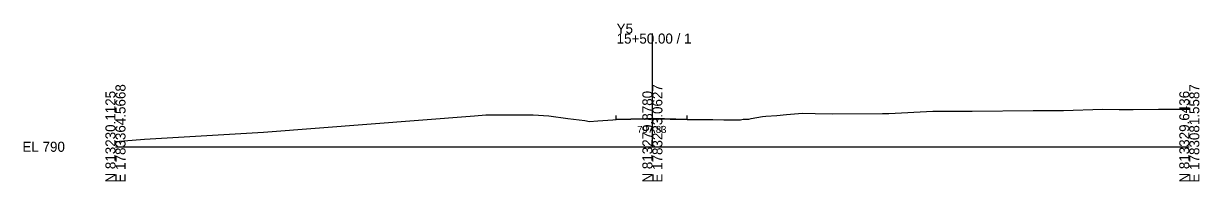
# Model space of a CAD drawing. Extents: x -26 to 1603, y -10 to 6526.
# Drawn here: x 1274.3 to 1602.8, y 2490.3 to 2534.4 of the extents above; entities that cross this region are included whole.
import ezdxf

# ---------------------------------------------------------------- set-up
doc = ezdxf.new("R2010")
doc.units = 0
for name, color, linetype in [('Exist Cross Section Cell', 7, 'Continuous'), ('Exist XS Center Line Elevation Label', 7, 'Continuous'), ('Exist XS Ground Line', 7, 'Continuous'), ('Prop XS EOT Tick Mark', 7, 'Continuous'), ('Prop XS Finish Grade Pavement', 7, 'Continuous')]:
    doc.layers.add(name, color=color, linetype=linetype)

msp = doc.modelspace()

# ---------------------------------------------------------------- linework, layer by layer
at = {"layer": 'Exist Cross Section Cell'}
for p, q in [((1450, 2500), (1450, 2531.62)), ((1300, 2500), (1450, 2500)), ((1450, 2500), (1600, 2500))]:
    msp.add_line(p, q, dxfattribs=at)
at = {"layer": 'Exist XS Ground Line'}
for p, q in [((1528.38, 2509.91), (1535.36, 2509.99)), ((1535.36, 2509.99), (1539.38, 2509.98)), ((1539.38, 2509.98), (1556.34, 2510.1)), ((1556.34, 2510.1), (1561.19, 2510.12)), ((1561.19, 2510.12), (1564.88, 2510.16)), ((1564.88, 2510.16), (1575.76, 2510.48)), ((1575.76, 2510.48), (1580.4, 2510.38)), ((1580.4, 2510.38), (1584.29, 2510.42)), ((1584.29, 2510.42), (1591.41, 2510.54)), ((1591.41, 2510.54), (1600, 2510.51)), ((1341.36, 2504.09), (1400.33, 2508.66)), ((1400.33, 2508.66), (1403.42, 2508.88)), ((1403.42, 2508.88), (1403.84, 2508.88)), ((1403.84, 2508.88), (1414.59, 2508.96)), ((1414.59, 2508.96), (1416.69, 2508.9)), ((1416.69, 2508.9), (1421.08, 2508.67)), ((1421.08, 2508.67), (1426.36, 2507.91)), ((1426.36, 2507.91), (1431.15, 2507.31)), ((1431.15, 2507.31), (1432.46, 2507.07)), ((1432.46, 2507.07), (1434.73, 2507.29)), ((1434.73, 2507.29), (1437.51, 2507.44)), ((1437.51, 2507.44), (1438.92, 2507.57)), ((1438.92, 2507.57), (1439.92, 2507.62)), ((1439.92, 2507.62), (1448.05, 2507.8)), ((1448.05, 2507.8), (1449.92, 2507.83)), ((1449.92, 2507.83), (1450.25, 2507.82)), ((1450.25, 2507.82), (1459.7, 2507.62)), ((1459.7, 2507.62), (1465.12, 2507.66)), ((1465.12, 2507.66), (1466.84, 2507.58)), ((1466.84, 2507.58), (1469.91, 2507.48)), ((1469.91, 2507.48), (1474.59, 2507.57)), ((1474.59, 2507.57), (1475.39, 2507.69)), ((1475.39, 2507.69), (1476.98, 2507.72)), ((1476.98, 2507.72), (1477.56, 2507.86)), ((1477.56, 2507.86), (1480.72, 2508.48)), ((1480.72, 2508.48), (1481.71, 2508.56)), ((1481.71, 2508.56), (1484.75, 2508.78)), ((1484.75, 2508.78), (1487.44, 2509.05)), ((1487.44, 2509.05), (1491.94, 2509.35)), ((1491.94, 2509.35), (1495.46, 2509.29)), ((1495.46, 2509.29), (1500.19, 2509.19)), ((1500.19, 2509.19), (1514.26, 2509.25)), ((1514.26, 2509.25), (1516.09, 2509.32)), ((1516.09, 2509.32), (1528.38, 2509.91)), ((1308.15, 2502.1), (1341.36, 2504.09)), ((1300, 2501.43), (1308.15, 2502.1))]:
    msp.add_line(p, q, dxfattribs=at)
at = {"layer": 'Prop XS EOT Tick Mark'}
for p, q in [((1439.89, 2507.74), (1439.89, 2508.74)), ((1459.69, 2507.75), (1459.69, 2508.75))]:
    msp.add_line(p, q, dxfattribs=at)
at = {"layer": 'Prop XS Finish Grade Pavement'}
for p, q in [((1439.89, 2507.74), (1439.91, 2507.75)), ((1439.91, 2507.75), (1448.04, 2507.92)), ((1448.04, 2507.92), (1449.92, 2507.96)), ((1449.92, 2507.96), (1450.25, 2507.95)), ((1450.25, 2507.95), (1459.69, 2507.75))]:
    msp.add_line(p, q, dxfattribs=at)

# ---------------------------------------------------------------- texts
at = {"layer": 'Exist Cross Section Cell'}
for s, p in [('Y5', (1440, 2531.62)), ('15+50.00 / 1', (1440, 2528.82)), ('EL 790', (1274, 2498.6))]:
    msp.add_text(s, height=2.8, dxfattribs=at).set_placement(p)
for s, p in [('E 1783364.5668', (1302.8, 2490)), ('E 1783223.0627', (1452.8, 2490)), ('E 1783081.5587', (1602.8, 2490)), ('N 813230.1125', (1300, 2490)), ('N 813279.8780', (1450, 2490)), ('N 813329.6436', (1600, 2490))]:
    msp.add_text(s, height=2.8, rotation=90, dxfattribs=at).set_placement(p)
at = {"layer": 'Exist XS Center Line Elevation Label'}
msp.add_text('797.83', height=2, dxfattribs=at).set_placement((1445.75, 2503.83))

doc.saveas('drawing.dxf')
